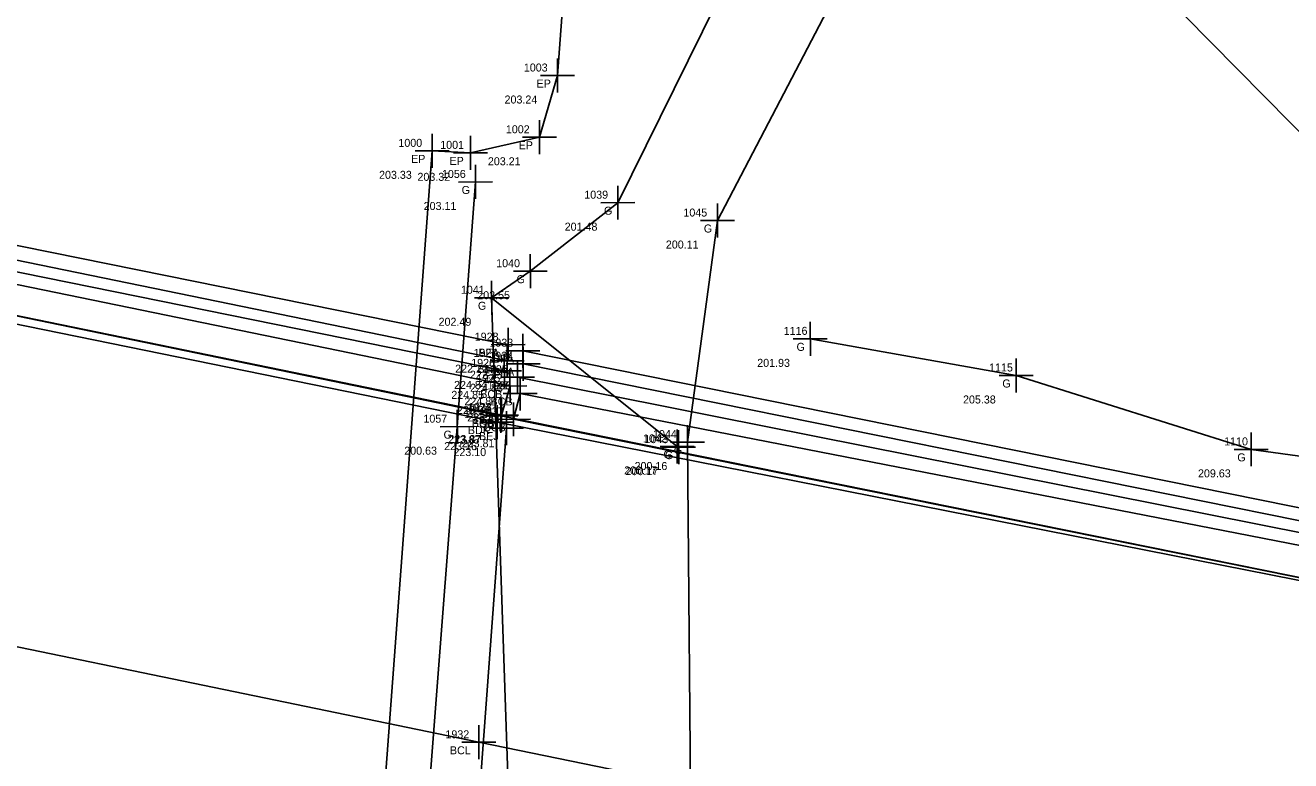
# Model space of a CAD drawing. Extents: x 1158983 to 1160032, y 610902 to 611573.
# Drawn here: x 1159613.25 to 1159660.69, y 611216.31 to 611243.89 of the extents above; entities that cross this region are included whole.
import ezdxf

# ---------------------------------------------------------------- set-up
doc = ezdxf.new("R2010")
doc.units = 0
for name, color, linetype in [('S_Bridge_Centerline', 7, 'Continuous'), ('S_Bridge_Curb', 7, 'Continuous'), ('S_Bridge_Deck', 7, 'Continuous'), ('S_Bridge_ExpansionJoint', 7, 'Continuous'), ('S_Bridge_Fascia', 7, 'Continuous'), ('S_Field_Code', 7, 'Continuous'), ('S_Ground_Elevation', 7, 'Continuous'), ('S_Guardrail_Beam', 7, 'Continuous'), ('S_Misc_MiscFeature', 7, 'Continuous'), ('S_Point_Elevation', 7, 'Continuous'), ('S_Point_Name', 7, 'Continuous'), ('S_Roadway_Edge_Pavement', 7, 'Continuous'), ('S_Survey_Shot', 7, 'Continuous')]:
    doc.layers.add(name, color=color, linetype=linetype)

msp = doc.modelspace()

# ---------------------------------------------------------------- linework, layer by layer
at = {"layer": 'S_Bridge_Centerline'}
msp.add_lwpolyline([(1159333.27, 611277.49), (1159375.085, 611269.079), (1159432.648, 611257.515), (1159502.769, 611243.159), (1159572.889, 611228.86), (1159630.259, 611216.999), (1159672.294, 611208.379)], dxfattribs=at)
at = {"layer": 'S_Bridge_Curb'}
for points in [[(1159574.307, 611242.109), (1159574.222, 611240.957), (1159631.107, 611229.274), (1159631.425, 611230.363)], [(1159631.81, 611230.082), (1159631.553, 611229.113), (1159674.182, 611220.519), (1159674.317, 611221.788)]]:
    msp.add_lwpolyline(points, close=True, dxfattribs=at)
at = {"layer": 'S_Bridge_Deck'}
msp.add_lwpolyline([(1159333.801, 611289.348), (1159375.965, 611280.699), (1159433.546, 611269.247), (1159503.551, 611254.972), (1159573.652, 611240.691), (1159630.945, 611229.008), (1159674.004, 611220.503), (1159672.341, 611196.28), (1159630.068, 611204.797), (1159572.75, 611216.514), (1159502.493, 611230.859), (1159432.439, 611245.062), (1159375.072, 611256.503), (1159331.888, 611265.329)], close=True, dxfattribs=at)
at = {"layer": 'S_Bridge_ExpansionJoint'}
msp.add_lwpolyline([(1159631.293, 611228.785), (1159629.57, 611205.385)], dxfattribs=at)
at = {"layer": 'S_Bridge_Fascia'}
for points in [[(1159574.585, 611243.396), (1159574.515, 611242.974), (1159631.316, 611231.303), (1159631.357, 611231.913)], [(1159631.909, 611231.686), (1159631.917, 611231.196), (1159674.346, 611222.618), (1159674.49, 611223.065)]]:
    msp.add_lwpolyline(points, close=True, dxfattribs=at)
at = {"layer": 'S_Ground_Elevation'}
for points in [[(1159699.879, 611547.889), (1159689.138, 611505.39), (1159682.19, 611468.661), (1159675.447, 611412.614), (1159667.959, 611368.602), (1159662.563, 611315.776), (1159650.73, 611269.469), (1159644.978, 611256.496), (1159635.463, 611237.238), (1159632.186, 611234.668), (1159630.736, 611233.672), (1159637.691, 611228.098), (1159637.746, 611228.069)], [(1159638.083, 611228.261), (1159639.206, 611236.569), (1159646.392, 611250.354), (1159655.57, 611262.055), (1159665.81, 611272.316), (1159673.6, 611274.458), (1159687.855, 611276.724), (1159696.119, 611275.149)], [(1159684.426, 611222.626), (1159676.582, 611228.372), (1159671.969, 611231.69), (1159663.682, 611237.191), (1159655.715, 611245.289), (1159649.225, 611248.009)], [(1159630.127, 611238.015), (1159629.448, 611228.837), (1159627.645, 611205.454), (1159627.406, 611201.758), (1159626.601, 611192.763), (1159626.636, 611192.293)], [(1159631.631, 611207.348), (1159630.736, 611233.672)], [(1159671.451, 611224.564), (1159669.545, 611226.568), (1159659.204, 611227.986), (1159650.394, 611230.757), (1159642.681, 611232.131)], [(1159638.219, 611212.373), (1159638.083, 611228.261)]]:
    msp.add_lwpolyline(points, dxfattribs=at)
at = {"layer": 'S_Guardrail_Beam'}
for p, q in [((1159573.73, 611241.065), (1159631.08, 611229.246)), ((1159631.08, 611229.246), (1159674.182, 611220.519))]:
    msp.add_line(p, q, dxfattribs=at)
at = {"layer": 'S_Misc_MiscFeature'}
for points in [[(1159574.426, 611242.456), (1159631.212, 611230.93)], [(1159631.705, 611230.691), (1159674.288, 611222.234)]]:
    msp.add_lwpolyline(points, dxfattribs=at)
at = {"layer": 'S_Roadway_Edge_Pavement'}
for points in [[(1159628.504, 611239.183), (1159629.944, 611239.108), (1159632.534, 611239.692), (1159633.209, 611242.008), (1159635.253, 611269.649), (1159639.894, 611315.426), (1159642.956, 611353.662), (1159646.64, 611401.094), (1159650.364, 611445.678), (1159654.56, 611495.47), (1159658.914, 611548.322)], [(1159628.504, 611239.183), (1159626.722, 611215.216)]]:
    msp.add_lwpolyline(points, dxfattribs=at)
at = {"layer": 'S_Survey_Shot'}
for p, q in [((1159633.21, 611241.372), (1159633.208, 611242.645)), ((1159632.573, 611242.007), (1159633.845, 611242.01)), ((1159633.209, 611242.008), (1159633.209, 611242.008)), ((1159632.536, 611239.055), (1159632.533, 611240.328)), ((1159628.505, 611238.547), (1159628.502, 611239.819)), ((1159629.945, 611238.472), (1159629.943, 611239.745)), ((1159631.898, 611239.69), (1159633.171, 611239.693)), ((1159632.534, 611239.692), (1159632.534, 611239.692)), ((1159627.867, 611239.182), (1159629.14, 611239.184)), ((1159628.504, 611239.183), (1159628.504, 611239.183)), ((1159629.308, 611239.107), (1159630.58, 611239.11)), ((1159629.944, 611239.108), (1159629.944, 611239.108)), ((1159630.129, 611237.379), (1159630.126, 611238.652)), ((1159629.491, 611238.014), (1159630.763, 611238.017)), ((1159630.127, 611238.015), (1159630.127, 611238.015)), ((1159635.464, 611236.602), (1159635.462, 611237.874)), ((1159634.827, 611237.237), (1159636.099, 611237.24)), ((1159635.463, 611237.238), (1159635.463, 611237.238)), ((1159639.208, 611235.933), (1159639.205, 611237.205)), ((1159638.57, 611236.567), (1159639.843, 611236.57)), ((1159639.206, 611236.569), (1159639.206, 611236.569)), ((1159632.188, 611234.032), (1159632.185, 611235.304)), ((1159631.55, 611234.667), (1159632.823, 611234.669)), ((1159632.186, 611234.668), (1159632.186, 611234.668)), ((1159630.737, 611233.036), (1159630.734, 611234.308)), ((1159630.099, 611233.671), (1159631.372, 611233.674)), ((1159630.736, 611233.672), (1159630.736, 611233.672)), ((1159631.359, 611231.276), (1159631.356, 611232.549)), ((1159642.683, 611231.495), (1159642.68, 611232.768)), ((1159631.91, 611231.05), (1159631.907, 611232.323)), ((1159642.045, 611232.13), (1159643.317, 611232.133)), ((1159642.681, 611232.131), (1159642.681, 611232.131)), ((1159630.721, 611231.911), (1159631.993, 611231.914)), ((1159631.214, 611230.294), (1159631.211, 611231.566)), ((1159631.272, 611231.685), (1159632.545, 611231.688)), ((1159631.318, 611230.667), (1159631.315, 611231.939)), ((1159631.357, 611231.913), (1159631.357, 611231.913)), ((1159631.909, 611231.686), (1159631.909, 611231.686)), ((1159631.918, 611230.56), (1159631.916, 611231.832)), ((1159630.68, 611231.302), (1159631.953, 611231.305)), ((1159631.281, 611231.195), (1159632.553, 611231.197)), ((1159631.316, 611231.303), (1159631.316, 611231.303)), ((1159631.706, 611230.055), (1159631.703, 611231.327)), ((1159631.917, 611231.196), (1159631.917, 611231.196)), ((1159650.396, 611230.121), (1159650.393, 611231.393)), ((1159630.576, 611230.929), (1159631.849, 611230.931)), ((1159631.068, 611230.69), (1159632.341, 611230.692)), ((1159631.212, 611230.93), (1159631.212, 611230.93)), ((1159631.426, 611229.727), (1159631.423, 611231)), ((1159631.705, 611230.691), (1159631.705, 611230.691)), ((1159631.811, 611229.445), (1159631.809, 611230.718)), ((1159649.758, 611230.756), (1159651.031, 611230.759)), ((1159650.394, 611230.757), (1159650.394, 611230.757)), ((1159630.788, 611230.362), (1159632.061, 611230.365)), ((1159631.425, 611230.363), (1159631.425, 611230.363)), ((1159630.946, 611228.371), (1159630.944, 611229.644)), ((1159631.082, 611228.61), (1159631.079, 611229.882)), ((1159631.109, 611228.638), (1159631.106, 611229.91)), ((1159631.174, 611230.08), (1159632.446, 611230.083)), ((1159631.554, 611228.477), (1159631.552, 611229.749)), ((1159631.81, 611230.082), (1159631.81, 611230.082)), ((1159629.45, 611228.201), (1159629.447, 611229.473)), ((1159630.444, 611229.245), (1159631.717, 611229.247)), ((1159630.471, 611229.273), (1159631.744, 611229.275)), ((1159631.08, 611229.246), (1159631.08, 611229.246)), ((1159631.107, 611229.274), (1159631.107, 611229.274)), ((1159631.294, 611228.149), (1159631.291, 611229.422)), ((1159628.812, 611228.836), (1159630.085, 611228.838)), ((1159629.448, 611228.837), (1159629.448, 611228.837)), ((1159630.309, 611229.006), (1159631.581, 611229.009)), ((1159630.656, 611228.784), (1159631.929, 611228.787)), ((1159630.917, 611229.112), (1159632.189, 611229.114)), ((1159630.945, 611229.008), (1159630.945, 611229.008)), ((1159631.293, 611228.785), (1159631.293, 611228.785)), ((1159631.553, 611229.113), (1159631.553, 611229.113)), ((1159637.693, 611227.462), (1159637.69, 611228.734)), ((1159637.747, 611227.433), (1159637.744, 611228.706)), ((1159638.084, 611227.625), (1159638.081, 611228.897)), ((1159637.446, 611228.26), (1159638.719, 611228.262)), ((1159638.083, 611228.261), (1159638.083, 611228.261)), ((1159659.205, 611227.35), (1159659.203, 611228.622)), ((1159637.055, 611228.097), (1159638.328, 611228.099)), ((1159637.109, 611228.068), (1159638.382, 611228.071)), ((1159637.691, 611228.098), (1159637.691, 611228.098)), ((1159637.746, 611228.069), (1159637.746, 611228.069)), ((1159658.568, 611227.985), (1159659.84, 611227.987)), ((1159659.204, 611227.986), (1159659.204, 611227.986)), ((1159630.26, 611216.363), (1159630.258, 611217.636)), ((1159629.623, 611216.998), (1159630.895, 611217.001)), ((1159630.259, 611216.999), (1159630.259, 611216.999))]:
    msp.add_line(p, q, dxfattribs=at)

# ---------------------------------------------------------------- texts
at = {"layer": 'S_Field_Code'}
for s, p in [('EP', (1159632.422, 611241.558)), ('EP', (1159631.748, 611239.242)), ('EP', (1159627.717, 611238.733)), ('EP', (1159629.157, 611238.658)), ('G', (1159629.612, 611237.565)), ('G', (1159634.948, 611236.788)), ('G', (1159638.691, 611236.119)), ('G', (1159631.671, 611234.218)), ('G', (1159630.221, 611233.222)), ('BFA', (1159630.24, 611231.463)), ('BFA', (1159630.791, 611231.236)), ('G', (1159642.166, 611231.681)), ('BFA', (1159630.199, 611230.853)), ('BFA', (1159630.8, 611230.746)), ('ZZ', (1159630.412, 611230.48)), ('G', (1159649.88, 611230.307)), ('BCB', (1159630.31, 611229.913)), ('ZZ', (1159630.904, 611230.241)), ('BCB', (1159630.695, 611229.632)), ('G', (1159628.934, 611228.387)), ('BDK', (1159629.844, 611228.558)), ('BCB', (1159629.992, 611228.824)), ('GB', (1159630.265, 611228.796)), ('BCB', (1159630.438, 611228.663)), ('BEJ', (1159630.263, 611228.335)), ('G', (1159637.176, 611227.648)), ('G', (1159637.231, 611227.619)), ('G', (1159637.568, 611227.811)), ('G', (1159658.689, 611227.536)), ('BCL', (1159629.173, 611216.549))]:
    msp.add_text(s, height=0.3, dxfattribs=at).set_placement(p)
at = {"layer": 'S_Point_Elevation'}
for s, p in [('203.24', (1159631.22, 611240.958)), ('203.21', (1159630.595, 611238.642)), ('203.33', (1159626.515, 611238.133)), ('203.32', (1159627.955, 611238.058)), ('203.11', (1159628.188, 611236.965)), ('201.48', (1159633.474, 611236.188)), ('200.11', (1159637.267, 611235.519)), ('202.55', (1159630.197, 611233.618)), ('202.49', (1159628.747, 611232.622)), ('222.22', (1159629.368, 611230.863)), ('201.93', (1159640.692, 611231.081)), ('222.23', (1159629.92, 611230.636)), ('224.85', (1159629.224, 611229.88)), ('224.84', (1159629.327, 611230.253)), ('224.83', (1159629.928, 611230.146)), ('224.84', (1159629.716, 611229.641)), ('205.38', (1159648.406, 611229.707)), ('223.90', (1159629.436, 611229.313)), ('223.88', (1159629.821, 611229.032)), ('223.16', (1159628.956, 611227.958)), ('223.87', (1159629.091, 611228.196)), ('223.87', (1159629.118, 611228.224)), ('223.81', (1159629.614, 611228.063)), ('200.63', (1159627.46, 611227.787)), ('223.10', (1159629.304, 611227.735)), ('200.17', (1159635.702, 611227.048)), ('200.17', (1159635.757, 611227.019)), ('200.16', (1159636.094, 611227.211)), ('209.63', (1159657.215, 611226.936))]:
    msp.add_text(s, height=0.3, dxfattribs=at).set_placement(p)
at = {"layer": 'S_Point_Name'}
for s, p in [('1003', (1159631.943, 611242.158)), ('1002', (1159631.269, 611239.842)), ('1000', (1159627.24, 611239.333)), ('1001', (1159628.808, 611239.258)), ('1056', (1159628.873, 611238.166)), ('1039', (1159634.209, 611237.388)), ('1045', (1159637.924, 611236.719)), ('1040', (1159630.906, 611234.818)), ('1041', (1159629.583, 611233.822)), ('1116', (1159641.684, 611232.281)), ('1928', (1159630.101, 611232.063)), ('1933', (1159630.652, 611231.836)), ('1927', (1159630.057, 611231.453)), ('1934', (1159630.646, 611231.346)), ('1926', (1159629.97, 611231.08)), ('1935', (1159630.448, 611230.841)), ('1115', (1159649.384, 611230.907)), ('1925', (1159630.168, 611230.513)), ('1936', (1159630.568, 611230.232)), ('1924', (1159629.81, 611229.396)), ('1923', (1159629.851, 611229.424)), ('1057', (1159628.178, 611228.987)), ('1929', (1159629.703, 611229.158)), ('1930', (1159630.039, 611228.935)), ('1937', (1159630.294, 611229.263)), ('1044', (1159636.786, 611228.411)), ('1042', (1159636.409, 611228.248)), ('1043', (1159636.463, 611228.219)), ('1110', (1159658.195, 611228.136)), ('1932', (1159629.003, 611217.149))]:
    msp.add_text(s, height=0.3, dxfattribs=at).set_placement(p)

doc.saveas('drawing.dxf')
